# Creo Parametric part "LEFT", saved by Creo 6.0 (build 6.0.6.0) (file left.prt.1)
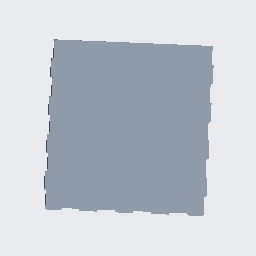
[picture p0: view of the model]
Units: Inch lbm Second (Pro/E Default); INCH, POUND, SECS

Created from: INLBS_PART_SOLID.PRT

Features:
  1. datum plane "RIGHT"
  2. datum plane "TOP"
  3. datum plane "FRONT"
  4. coordinate system
  5. sketch "Sketch 1"
  6. extrusion "Extrude 1"

Surfaces: 54 plane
